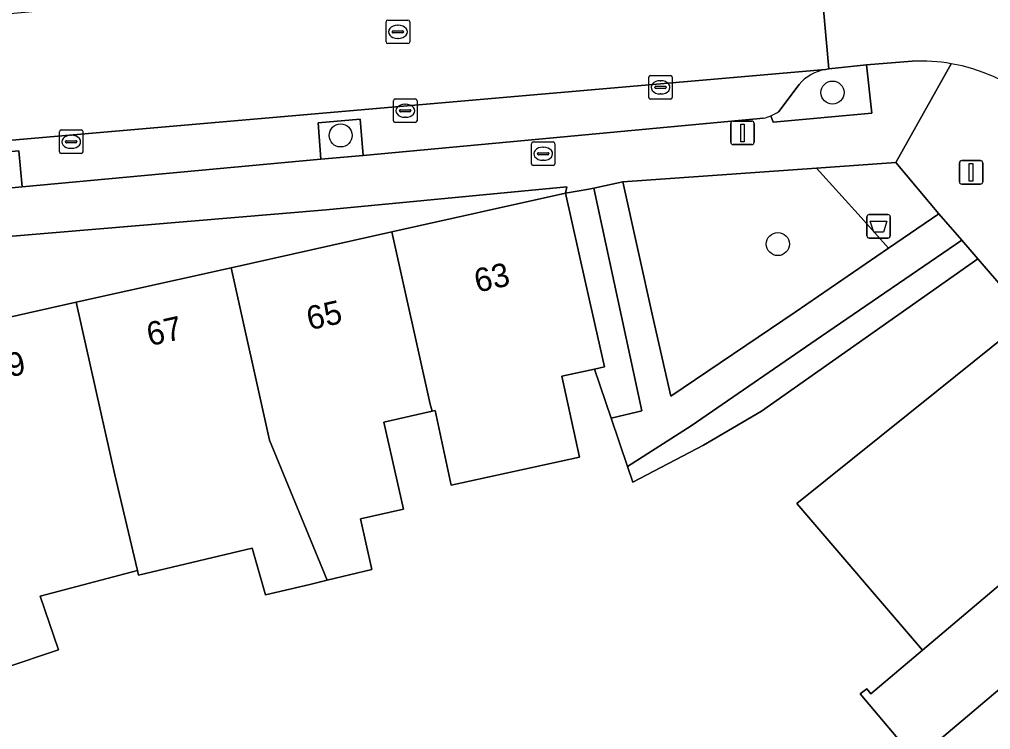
# Model space of a CAD drawing. Extents: x 160377 to 161131, y 383938 to 384853.
# Drawn here: x 160622.12 to 160663.39, y 384466.81 to 384496.99 of the extents above; entities that cross this region are included whole.
import ezdxf

# ---------------------------------------------------------------- set-up
doc = ezdxf.new("R2010")
doc.units = 0
for name, color, linetype in [('IMGEO_Afvalbak', 7, 'Continuous'), ('IMGEO_Boom', 7, 'Continuous'), ('IMGEO_Brandkraan', 7, 'Continuous'), ('IMGEO_Erf', 7, 'Continuous'), ('IMGEO_Groenvoorziening', 7, 'Continuous'), ('IMGEO_Hek', 7, 'Continuous'), ('IMGEO_Kolk', 7, 'Continuous'), ('IMGEO_Lichtmast', 7, 'Continuous'), ('IMGEO_Pand', 7, 'Continuous'), ('IMGEO_Pand_nummerreeks', 7, 'Continuous'), ('IMGEO_Parkeervlak_open', 7, 'Continuous'), ('IMGEO_Rijbaan_lokaal_open', 7, 'Continuous'), ('IMGEO_Rioolput', 7, 'Continuous'), ('IMGEO_Voetpad_open', 7, 'Continuous')]:
    doc.layers.add(name, color=color, linetype=linetype)

msp = doc.modelspace()

# ---------------------------------------------------------------- linework, layer by layer
at = {"layer": 'IMGEO_Afvalbak'}
for p, q in [((160658.132, 384487.799), (160658.132, 384488.599)), ((160658.132, 384488.599), (160658.132, 384487.799)), ((160658.232, 384488.699), (160659.022, 384488.699)), ((160659.022, 384488.699), (160658.232, 384488.699)), ((160659.122, 384488.599), (160659.122, 384487.799)), ((160659.122, 384487.799), (160659.122, 384488.599)), ((160659.022, 384487.699), (160658.232, 384487.699)), ((160658.232, 384487.699), (160659.022, 384487.699))]:
    msp.add_line(p, q, dxfattribs=at)
msp.add_lwpolyline([(160658.275, 384488.413), (160658.979, 384488.413), (160658.83, 384487.943), (160658.424, 384487.943), (160658.275, 384488.413)], dxfattribs=at)
for centre, start, end in [((160658.232, 384488.599), 90, 180), ((160658.232, 384488.599), 90, 180), ((160659.022, 384488.599), 0, 90), ((160659.022, 384488.599), 360, 90), ((160658.232, 384487.799), 180, 270), ((160658.232, 384487.799), 180, 270), ((160659.022, 384487.799), 270, 0), ((160659.022, 384487.799), 270, 0)]:
    msp.add_arc(centre, 0.1, start, end, dxfattribs=at)
at = {"layer": 'IMGEO_Boom'}
for centre in [(160656.669, 384493.883), (160635.77, 384492.059), (160654.346, 384487.443)]:
    msp.add_circle(centre, 0.489, dxfattribs=at)
at = {"layer": 'IMGEO_Brandkraan'}
for p, q in [((160643.876, 384490.858), (160643.876, 384491.71)), ((160643.951, 384491.784), (160644.803, 384491.784)), ((160644.364, 384491.564), (160644.389, 384491.564)), ((160644.877, 384491.71), (160644.877, 384490.858)), ((160644.135, 384491.278), (160644.135, 384491.29)), ((160644.573, 384491.241), (160644.175, 384491.241)), ((160644.178, 384491.327), (160644.576, 384491.327)), ((160644.387, 384491.004), (160644.362, 384491.004)), ((160644.619, 384491.29), (160644.619, 384491.278)), ((160644.803, 384490.784), (160643.951, 384490.784))]:
    msp.add_line(p, q, dxfattribs=at)
for points in [[(160643.876, 384490.858), (160643.876, 384491.71)], [(160643.951, 384491.784), (160644.803, 384491.784)], [(160644.877, 384491.71), (160644.877, 384490.858)], [(160644.803, 384490.784), (160643.951, 384490.784)]]:
    msp.add_lwpolyline(points, dxfattribs=at)
for centre, radius, start, end in [((160643.953, 384491.708), 0.0765, 91.552, 178.448), ((160643.953, 384491.708), 0.0765, 91.552, 178.448), ((160644.801, 384491.708), 0.0765, 1.552, 88.448), ((160644.801, 384491.708), 0.0765, 1.552, 88.448), ((160644.175, 384491.287), 0.0403, 85.8775, 175.7526), ((160644.172, 384491.277), 0.0366, 178.938, 274.7102), ((160644.576, 384491.284), 0.043, 264.8664, 352.4533), ((160644.58, 384491.289), 0.0386, 1.7309, 96.639), ((160643.953, 384490.86), 0.0765, 181.552, 268.448), ((160643.953, 384490.86), 0.0765, 181.552, 268.448), ((160644.801, 384490.86), 0.0765, 271.552, 358.448), ((160644.801, 384490.86), 0.0765, 271.552, 358.448)]:
    msp.add_arc(centre, radius, start, end, dxfattribs=at)
for centre, major_axis, ratio, start_param, end_param in [((160644.363, 384491.284), (-0.387, 0.002), 0.722429, 4.712389, 7.853982), ((160644.388, 384491.284), (-0.39, 0.002), 0.717154, 1.570796, 4.712389)]:
    msp.add_ellipse(centre, major_axis=major_axis, ratio=ratio, start_param=start_param, end_param=end_param, dxfattribs=at)
at = {"layer": 'IMGEO_Erf'}
msp.add_lwpolyline([(160631.118, 384486.438), (160637.94, 384487.959), (160645.328, 384489.607), (160645.381, 384489.88), (160635.158, 384488.897), (160605.786, 384486.439), (160606.386, 384480.921), (160617.606, 384483.424), (160624.536, 384484.97)], close=True, dxfattribs=at)
msp.add_lwpolyline([(160664.154, 384468.861), (160660.211, 384465.528), (160657.839, 384468.334), (160658.124, 384468.542), (160658.296, 384468.339), (160660.489, 384470.193), (160655.155, 384476.426), (160661.101, 384481.192), (160665.002, 384484.318), (160662.841, 384486.817), (160653.656, 384480.346), (160651.181, 384478.897), (160648.181, 384477.331), (160647.958, 384477.99), (160647.265, 384480.041), (160646.559, 384482.135), (160645.166, 384481.831), (160645.915, 384478.392), (160640.473, 384477.206), (160639.784, 384480.366), (160639.653, 384480.337), (160637.612, 384479.879), (160638.443, 384476.173), (160636.608, 384475.762), (160637.089, 384473.616), (160635.192, 384473.161), (160634.456, 384472.984), (160632.579, 384472.533), (160632.013, 384474.528), (160627.184, 384473.369), (160627.134, 384473.579), (160623.006, 384472.489), (160623.782, 384470.208), (160621.508, 384469.435)], dxfattribs=at)
at = {"layer": 'IMGEO_Groenvoorziening'}
for points in [[(160654.048, 384492.894), (160654.141, 384492.63), (160658.334, 384493.001), (160658.107, 384495.062)], [(160658.107, 384495.062), (160656.518, 384494.884), (160656.376, 384494.864)], [(160655.247, 384494.228), (160654.386, 384493.076)]]:
    msp.add_lwpolyline(points, dxfattribs=at)
for points in [[(160634.933, 384491.047), (160636.722, 384491.213), (160636.596, 384492.753), (160634.814, 384492.597)], [(160620.441, 384489.706), (160622.235, 384489.872), (160622.101, 384491.401), (160620.313, 384491.248)], [(160659.047, 384487.268), (160657.885, 384488.568), (160655.984, 384490.668), (160647.758, 384490.083), (160649.038, 384484.332), (160649.803, 384480.983), (160655.087, 384484.557)], [(160646.525, 384489.816), (160646.315, 384489.771), (160645.328, 384489.607), (160646.161, 384485.873), (160646.983, 384482.227), (160646.559, 384482.135), (160647.265, 384480.041), (160648.398, 384480.312), (160648.571, 384480.353)], [(160662.841, 384486.817), (160662.165, 384487.613), (160656.203, 384483.534), (160650.658, 384479.717), (160647.958, 384477.99), (160648.181, 384477.331), (160651.181, 384478.897), (160653.656, 384480.346)]]:
    msp.add_lwpolyline(points, close=True, dxfattribs=at)
for centre, radius, start, end in [((160656.706, 384492.959), 1.934, 99.8164, 138.9713), ((160653.242, 384494.795), 2.065, 292.9672, 303.6343)]:
    msp.add_arc(centre, radius, start, end, dxfattribs=at)
at = {"layer": 'IMGEO_Hek'}
msp.add_lwpolyline([(160653.656, 384480.346), (160662.841, 384486.817)], dxfattribs=at)
at = {"layer": 'IMGEO_Kolk'}
for p, q in [((160648.861, 384493.678), (160648.861, 384494.53)), ((160648.936, 384494.604), (160649.788, 384494.604)), ((160649.349, 384494.384), (160649.374, 384494.384)), ((160649.862, 384494.53), (160649.862, 384493.678)), ((160649.12, 384494.098), (160649.12, 384494.11)), ((160649.558, 384494.061), (160649.16, 384494.061)), ((160649.163, 384494.147), (160649.561, 384494.147)), ((160649.604, 384494.11), (160649.604, 384494.098)), ((160638.014, 384492.684), (160638.014, 384493.536)), ((160638.089, 384493.61), (160638.941, 384493.61)), ((160639.015, 384493.536), (160639.015, 384492.684)), ((160649.788, 384493.604), (160648.936, 384493.604)), ((160649.372, 384493.824), (160649.347, 384493.824)), ((160638.273, 384493.104), (160638.273, 384493.116)), ((160638.711, 384493.067), (160638.313, 384493.067)), ((160638.316, 384493.153), (160638.714, 384493.153)), ((160638.502, 384493.39), (160638.527, 384493.39)), ((160638.757, 384493.116), (160638.757, 384493.104)), ((160638.525, 384492.83), (160638.5, 384492.83)), ((160623.821, 384491.366), (160623.821, 384492.218)), ((160623.896, 384492.292), (160624.748, 384492.292)), ((160624.822, 384492.218), (160624.822, 384491.366)), ((160638.941, 384492.61), (160638.089, 384492.61)), ((160624.123, 384491.835), (160624.521, 384491.835)), ((160624.309, 384492.072), (160624.334, 384492.072)), ((160624.08, 384491.786), (160624.08, 384491.798)), ((160624.518, 384491.749), (160624.12, 384491.749)), ((160624.332, 384491.512), (160624.307, 384491.512)), ((160624.564, 384491.798), (160624.564, 384491.786)), ((160624.748, 384491.292), (160623.896, 384491.292))]:
    msp.add_line(p, q, dxfattribs=at)
for points in [[(160648.861, 384493.678), (160648.861, 384494.53)], [(160648.936, 384494.604), (160649.788, 384494.604)], [(160649.862, 384494.53), (160649.862, 384493.678)], [(160638.014, 384492.684), (160638.014, 384493.536)], [(160638.089, 384493.61), (160638.941, 384493.61)], [(160639.015, 384493.536), (160639.015, 384492.684)], [(160649.788, 384493.604), (160648.936, 384493.604)], [(160623.821, 384491.366), (160623.821, 384492.218)], [(160623.896, 384492.292), (160624.748, 384492.292)], [(160624.822, 384492.218), (160624.822, 384491.366)], [(160638.941, 384492.61), (160638.089, 384492.61)], [(160624.748, 384491.292), (160623.896, 384491.292)]]:
    msp.add_lwpolyline(points, dxfattribs=at)
for centre, radius, start, end in [((160648.938, 384494.528), 0.0765, 91.552, 178.448), ((160648.938, 384494.528), 0.0765, 91.552, 178.448), ((160649.786, 384494.528), 0.0765, 1.552, 88.448), ((160649.786, 384494.528), 0.0765, 1.552, 88.448), ((160649.16, 384494.107), 0.0403, 85.8775, 175.7526), ((160649.157, 384494.097), 0.0366, 178.938, 274.7102), ((160649.561, 384494.104), 0.043, 264.8664, 352.4533), ((160649.565, 384494.109), 0.0386, 1.7309, 96.639), ((160638.091, 384493.534), 0.0765, 91.552, 178.448), ((160638.091, 384493.534), 0.0765, 91.552, 178.448), ((160638.939, 384493.534), 0.0765, 1.552, 88.448), ((160638.939, 384493.534), 0.0765, 1.552, 88.448), ((160648.938, 384493.68), 0.0765, 181.552, 268.448), ((160648.938, 384493.68), 0.0765, 181.552, 268.448), ((160649.786, 384493.68), 0.0765, 271.552, 358.448), ((160649.786, 384493.68), 0.0765, 271.552, 358.448), ((160638.313, 384493.113), 0.0403, 85.8775, 175.7526), ((160638.31, 384493.103), 0.0366, 178.938, 274.7102), ((160638.714, 384493.11), 0.043, 264.8664, 352.4533), ((160638.718, 384493.115), 0.0386, 1.7309, 96.639), ((160638.091, 384492.686), 0.0765, 181.552, 268.448), ((160638.091, 384492.686), 0.0765, 181.552, 268.448), ((160638.939, 384492.686), 0.0765, 271.552, 358.448), ((160638.939, 384492.686), 0.0765, 271.552, 358.448), ((160623.898, 384492.216), 0.0765, 91.552, 178.448), ((160623.898, 384492.216), 0.0765, 91.552, 178.448), ((160624.746, 384492.216), 0.0765, 1.552, 88.448), ((160624.746, 384492.216), 0.0765, 1.552, 88.448), ((160624.12, 384491.795), 0.0403, 85.8775, 175.7526), ((160624.525, 384491.797), 0.0386, 1.7309, 96.639), ((160624.117, 384491.785), 0.0366, 178.938, 274.7102), ((160624.521, 384491.792), 0.043, 264.8664, 352.4533), ((160623.898, 384491.368), 0.0765, 181.552, 268.448), ((160623.898, 384491.368), 0.0765, 181.552, 268.448), ((160624.746, 384491.368), 0.0765, 271.552, 358.448), ((160624.746, 384491.368), 0.0765, 271.552, 358.448)]:
    msp.add_arc(centre, radius, start, end, dxfattribs=at)
for centre, major_axis, ratio, start_param, end_param in [((160649.348, 384494.104), (-0.387, 0.002), 0.722429, 4.712389, 7.853982), ((160649.373, 384494.104), (-0.39, 0.002), 0.717154, 1.570796, 4.712389), ((160638.501, 384493.11), (-0.387, 0.002), 0.722429, 4.712389, 7.853982), ((160638.526, 384493.11), (-0.39, 0.002), 0.717154, 1.570796, 4.712389), ((160624.308, 384491.792), (-0.387, 0.002), 0.722429, 4.712389, 7.853982), ((160624.333, 384491.792), (-0.39, 0.002), 0.717154, 1.570796, 4.712389)]:
    msp.add_ellipse(centre, major_axis=major_axis, ratio=ratio, start_param=start_param, end_param=end_param, dxfattribs=at)
at = {"layer": 'IMGEO_Lichtmast'}
for p, q in [((160652.448, 384492.67), (160653.238, 384492.67)), ((160653.238, 384492.67), (160652.448, 384492.67)), ((160652.348, 384491.77), (160652.348, 384492.57)), ((160652.348, 384492.57), (160652.348, 384491.77)), ((160653.338, 384492.57), (160653.338, 384491.77)), ((160653.338, 384491.77), (160653.338, 384492.57)), ((160653.238, 384491.67), (160652.448, 384491.67)), ((160652.448, 384491.67), (160653.238, 384491.67)), ((160662.163, 384490.992), (160662.953, 384490.992)), ((160662.953, 384490.992), (160662.163, 384490.992)), ((160662.063, 384490.092), (160662.063, 384490.892)), ((160662.063, 384490.892), (160662.063, 384490.092)), ((160663.053, 384490.892), (160663.053, 384490.092)), ((160663.053, 384490.092), (160663.053, 384490.892)), ((160662.953, 384489.992), (160662.163, 384489.992)), ((160662.163, 384489.992), (160662.953, 384489.992))]:
    msp.add_line(p, q, dxfattribs=at)
for points in [[(160652.768, 384492.545), (160652.918, 384492.545), (160652.918, 384491.795), (160652.768, 384491.795), (160652.768, 384492.545)], [(160662.483, 384490.867), (160662.633, 384490.867), (160662.633, 384490.117), (160662.483, 384490.117), (160662.483, 384490.867)]]:
    msp.add_lwpolyline(points, dxfattribs=at)
for centre, start, end in [((160652.448, 384492.57), 90, 180), ((160652.448, 384492.57), 90, 180), ((160653.238, 384492.57), 0, 90), ((160653.238, 384492.57), 360, 90), ((160652.448, 384491.77), 180, 270), ((160652.448, 384491.77), 180, 270), ((160653.238, 384491.77), 270, 0), ((160653.238, 384491.77), 270, 0), ((160662.163, 384490.892), 90, 180), ((160662.163, 384490.892), 90, 180), ((160662.953, 384490.892), 0, 90), ((160662.953, 384490.892), 360, 90), ((160662.163, 384490.092), 180, 270), ((160662.163, 384490.092), 180, 270), ((160662.953, 384490.092), 270, 0), ((160662.953, 384490.092), 270, 0)]:
    msp.add_arc(centre, 0.1, start, end, dxfattribs=at)
at = {"layer": 'IMGEO_Pand'}
for points in [[(160639.653, 384480.337), (160639.784, 384480.366), (160640.473, 384477.206), (160645.915, 384478.392), (160645.166, 384481.831), (160646.559, 384482.135), (160646.983, 384482.227), (160646.161, 384485.873), (160645.328, 384489.607), (160637.94, 384487.959), (160639.575, 384480.635)], [(160639.653, 384480.337), (160639.575, 384480.635), (160637.94, 384487.959), (160631.118, 384486.438), (160632.753, 384479.113), (160635.192, 384473.161), (160637.089, 384473.616), (160636.608, 384475.762), (160638.443, 384476.173), (160637.612, 384479.879)], [(160632.753, 384479.113), (160631.118, 384486.438), (160624.536, 384484.97), (160626.171, 384477.645), (160627.134, 384473.579), (160627.184, 384473.369), (160632.013, 384474.528), (160632.579, 384472.533), (160634.456, 384472.984), (160635.192, 384473.161)], [(160626.171, 384477.645), (160624.536, 384484.97), (160617.606, 384483.424), (160619.24, 384476.099), (160620.667, 384471.908), (160621.508, 384469.435), (160623.782, 384470.208), (160623.006, 384472.489), (160627.134, 384473.579)], [(160670.063, 384478.286), (160665.002, 384484.318), (160661.101, 384481.192), (160655.155, 384476.426), (160660.489, 384470.193)], [(160674.74, 384472.775), (160670.49, 384477.782), (160670.063, 384478.286), (160660.489, 384470.193), (160658.296, 384468.339), (160658.124, 384468.542), (160657.839, 384468.334), (160660.211, 384465.528), (160664.154, 384468.861), (160666.059, 384466.608)]]:
    msp.add_lwpolyline(points, close=True, dxfattribs=at)
at = {"layer": 'IMGEO_Parkeervlak_open'}
for points in [[(160656.376, 384494.864), (160620.16, 384491.723), (160608.33, 384490.653), (160608.359, 384490.293), (160608.482, 384488.752), (160619.853, 384489.651), (160620.441, 384489.706), (160620.313, 384491.248), (160622.101, 384491.401), (160622.235, 384489.872), (160634.933, 384491.047), (160634.814, 384492.597), (160636.596, 384492.753), (160636.722, 384491.213)], [(160654.386, 384493.076), (160655.247, 384494.228)], [(160636.722, 384491.213), (160644.187, 384491.904), (160653.737, 384492.788)]]:
    msp.add_lwpolyline(points, dxfattribs=at)
for centre, radius, start, end in [((160656.706, 384492.959), 1.934, 99.8164, 138.9713), ((160653.242, 384494.795), 2.065, 292.9672, 303.6343), ((160653.222, 384494.807), 2.084, 284.2994, 293.3426)]:
    msp.add_arc(centre, radius, start, end, dxfattribs=at)
at = {"layer": 'IMGEO_Rijbaan_lokaal_open'}
msp.add_lwpolyline([(160681.08, 384497.44), (160684.957, 384497.974), (160686.513, 384498.219), (160686.58, 384498.232), (160685.714, 384503.375), (160683.364, 384502.943), (160682.351, 384502.826), (160681.144, 384502.714), (160666.223, 384501.382), (160656.868, 384500.475), (160656.011, 384500.414), (160656.518, 384494.884), (160658.107, 384495.062), (160660.061, 384495.216)], dxfattribs=at)
msp.add_lwpolyline([(160656.011, 384500.414), (160619.735, 384497.05), (160620.16, 384491.723), (160656.376, 384494.864), (160656.518, 384494.884)], close=True, dxfattribs=at)
for centre, radius, start, end in [((160660.371, 384487.343), 7.88, 80.1947, 92.2555), ((160660.373, 384487.413), 7.81, 25.3531, 80.1223)]:
    msp.add_arc(centre, radius, start, end, dxfattribs=at)
at = {"layer": 'IMGEO_Rioolput'}
for p, q in [((160637.702, 384496.035), (160637.702, 384496.887)), ((160637.777, 384496.961), (160638.629, 384496.961)), ((160638.703, 384496.887), (160638.703, 384496.035)), ((160637.961, 384496.455), (160637.961, 384496.467)), ((160638.399, 384496.418), (160638.001, 384496.418)), ((160638.004, 384496.504), (160638.402, 384496.504)), ((160638.19, 384496.741), (160638.215, 384496.741)), ((160638.445, 384496.467), (160638.445, 384496.455)), ((160638.629, 384495.961), (160637.777, 384495.961)), ((160638.213, 384496.181), (160638.188, 384496.181))]:
    msp.add_line(p, q, dxfattribs=at)
for points in [[(160637.702, 384496.035), (160637.702, 384496.887)], [(160637.777, 384496.961), (160638.629, 384496.961)], [(160638.703, 384496.887), (160638.703, 384496.035)], [(160638.629, 384495.961), (160637.777, 384495.961)]]:
    msp.add_lwpolyline(points, dxfattribs=at)
for centre, radius, start, end in [((160637.779, 384496.885), 0.0765, 91.552, 178.448), ((160637.779, 384496.885), 0.0765, 91.552, 178.448), ((160638.627, 384496.885), 0.0765, 1.552, 88.448), ((160638.627, 384496.885), 0.0765, 1.552, 88.448), ((160638.001, 384496.464), 0.0403, 85.8775, 175.7526), ((160637.998, 384496.454), 0.0366, 178.938, 274.7102), ((160638.402, 384496.461), 0.043, 264.8664, 352.4533), ((160638.406, 384496.466), 0.0386, 1.7309, 96.639), ((160637.779, 384496.037), 0.0765, 181.552, 268.448), ((160637.779, 384496.037), 0.0765, 181.552, 268.448), ((160638.627, 384496.037), 0.0765, 271.552, 358.448), ((160638.627, 384496.037), 0.0765, 271.552, 358.448)]:
    msp.add_arc(centre, radius, start, end, dxfattribs=at)
for centre, major_axis, ratio, start_param, end_param in [((160638.189, 384496.461), (-0.387, 0.002), 0.722429, 4.712389, 7.853982), ((160638.214, 384496.461), (-0.39, 0.002), 0.717154, 1.570796, 4.712389)]:
    msp.add_ellipse(centre, major_axis=major_axis, ratio=ratio, start_param=start_param, end_param=end_param, dxfattribs=at)
at = {"layer": 'IMGEO_Voetpad_open'}
for points in [[(160660.061, 384495.216), (160658.107, 384495.062), (160658.334, 384493.001), (160654.141, 384492.63), (160654.048, 384492.894)], [(160655.984, 384490.668), (160659.354, 384490.911), (160661.713, 384495.107)], [(160661.713, 384495.107), (160659.354, 384490.911), (160661.181, 384488.728), (160662.165, 384487.613), (160662.841, 384486.817), (160665.002, 384484.318), (160670.063, 384478.286), (160670.49, 384477.782), (160674.74, 384472.775), (160679.832, 384466.741)], [(160653.737, 384492.788), (160644.187, 384491.904), (160636.722, 384491.213), (160634.933, 384491.047), (160622.235, 384489.872), (160620.441, 384489.706)], [(160605.786, 384486.439), (160635.158, 384488.897), (160645.381, 384489.88), (160645.328, 384489.607), (160646.315, 384489.771), (160646.525, 384489.816), (160647.758, 384490.083), (160655.984, 384490.668)]]:
    msp.add_lwpolyline(points, dxfattribs=at)
for points in [[(160659.354, 384490.911), (160655.984, 384490.668), (160657.885, 384488.568), (160659.047, 384487.268), (160661.181, 384488.728)], [(160656.203, 384483.534), (160662.165, 384487.613), (160661.181, 384488.728), (160659.047, 384487.268), (160655.087, 384484.557), (160649.803, 384480.983), (160649.038, 384484.332), (160647.758, 384490.083), (160646.525, 384489.816), (160648.571, 384480.353), (160648.398, 384480.312), (160647.265, 384480.041), (160647.958, 384477.99), (160650.658, 384479.717)]]:
    msp.add_lwpolyline(points, close=True, dxfattribs=at)
for centre, radius, start, end in [((160660.371, 384487.343), 7.88, 80.1947, 92.2555), ((160660.373, 384487.413), 7.81, 25.3531, 80.1223), ((160653.222, 384494.807), 2.084, 284.2994, 293.3426)]:
    msp.add_arc(centre, radius, start, end, dxfattribs=at)

# ---------------------------------------------------------------- texts
at = {"layer": 'IMGEO_Pand_nummerreeks'}
for s, rotation, p in [('63', 12.6487, (160641.575, 384485.377)), ('65', 12.6487, (160634.45, 384483.778)), ('67', 12.5764, (160627.655, 384483.104)), ('69', 12.5764, (160620.994, 384481.619))]:
    msp.add_text(s, height=1, rotation=rotation, dxfattribs=at).set_placement(p)

doc.saveas('drawing.dxf')
